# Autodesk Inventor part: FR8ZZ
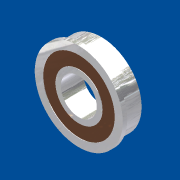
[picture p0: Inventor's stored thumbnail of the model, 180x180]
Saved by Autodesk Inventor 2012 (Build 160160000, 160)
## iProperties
Created: 2010-11
Part Number: FR8ZZ
Document SubType Name: Modeling
Designer: WaffleKing13
Density: 7.84 g/cm^3
Material: Steel, High Strength Low Alloy
Vendor: Andy Mark
Description: Half-inch sholder bearing
Stock Number: AM-0030
Mass: 32.7787 g
Surface Area: 23.5112 cm^2
Volume: 4.18096 cm^3
Author: WaffleKing13
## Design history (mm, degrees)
sketch "Sketch1"
  geometry: C1 r 6.35 at (0, 0); C2 r 8.255 at (0, 0); C3 r 14.287 at (0, 0); C4 r 12.7 at (0, 0); 1 further point
  constraints: 4 centre point, 4 coincident
  dimensions: "d0" = 16.51 diameter of C2; "d1" = 12.7 diameter of C1; "d2" = 28.575 diameter of C3; "d4" = 25.4 diameter of C4
extrude "Extrusion1" new body sketch "Sketch1" stored distance "d5" = 7.9375; taper "d6" = 0 deg
sketch "Sketch2"
  geometry: C1 r 12.7 at (0, 0) reference; C2 r 14.287 at (0, 0) reference; C3 r 15.558 at (0, 0); C4 r 14.287 at (0, 0)
  constraints: 4 coincident, 2 centre point, 1 concentric
  dimensions: "d7" = 31.115 diameter of C3
extrude "Extrusion2" join sketch "Sketch2" distance "d8" = 1.5875; taper "d9" = 0 deg
sketch "Sketch3"
  geometry: C1 r 12.7 at (0, 0); C2 r 8.255 at (0, 0); 1 further point
  constraints: 2 centre point, 2 coincident
  dimensions: "d10" = 16.51 diameter of C2; "d11" = 25.4 diameter of C1
extrude "Extrusion3" join sketch "Sketch3" stored distance "d12" = 7.62; taper "d13" = 0 deg
body "Solid1"
